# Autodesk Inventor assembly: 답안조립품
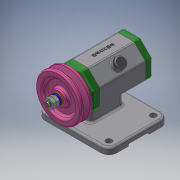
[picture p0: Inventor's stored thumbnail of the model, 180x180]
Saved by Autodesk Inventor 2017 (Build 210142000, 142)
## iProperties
Part Number: 답안조립품
Material: 일반
Document SubType Name: Assembly
Designer: MRC
Author: MRC
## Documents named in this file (16)
- C:\Users\MRC\Desktop\721006V1009\답안조립품.iam
- C:\Users\MRC\Desktop\721006V1009\본체.ipt
- C:\Users\MRC\Desktop\721006V1009\축.ipt
- C:\Users\MRC\Desktop\721006V1009\키 3x3x12.ipt
- 키 3x3x12.ipt
- C:\Users\MRC\Desktop\721006V1009\베어링 6002.ipt
- C:\Users\MRC\Desktop\721006V1009\앞커버.ipt
- C:\Users\MRC\Desktop\721006V1009\오일 실 15x25x7.ipt
- C:\Users\MRC\Desktop\721006V1009\뒤커버.ipt
- C:\Users\MRC\Desktop\721006V1009\볼트 M4x12.ipt
- C:\Users\MRC\Desktop\721006V1009\V벨트풀리.ipt
- C:\Users\MRC\Desktop\721006V1009\와셔 8x17.ipt
- C:\Users\MRC\Desktop\721006V1009\스프링와셔 8.ipt
- C:\Users\MRC\Desktop\721006V1009\너트 M8.ipt
- 너트 M8.ipt
- C:\Users\MRC\Desktop\721006V1009\고무캡.ipt
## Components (2 placed, 2 different names)
1. V벨트풀리:1
2. 고무캡:1
